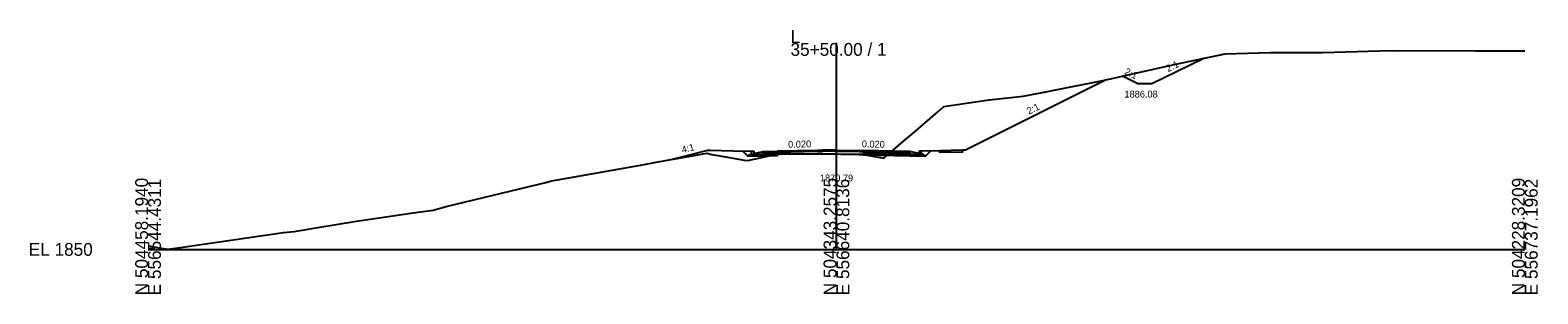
# Model space of a CAD drawing. Extents: x -26 to 4603, y -10 to 4703.
# Drawn here: x 974.3 to 1302.8, y 2685.3 to 2742.8 of the extents above; entities that cross this region are included whole.
import ezdxf

# ---------------------------------------------------------------- set-up
doc = ezdxf.new("R2010")
doc.units = 0
for name, color, linetype in [('Default', 7, 'Continuous'), ('Exist Cross Section Cell', 7, 'Continuous'), ('Exist XS Ground Line', 7, 'Continuous'), ('Prop CMT Pvmt Course 1', 7, 'Continuous'), ('Prop CMT Pvmt Course 2', 7, 'Continuous'), ('Prop CMT Pvmt Course 3', 7, 'Continuous'), ('Prop CMT Pvmt Milling', 7, 'Continuous'), ('Prop CMT Shear Line', 7, 'Continuous'), ('Prop CMT Shld Paved Course 2', 7, 'Continuous'), ('Prop CMT Shld Paved Course 3', 7, 'Continuous'), ('Prop CMT Subgrade Earthwork', 7, 'Continuous'), ('Prop Conc 4in Sidewalk', 7, 'Continuous'), ('Prop Conc Curb and Gutter', 7, 'Continuous'), ('Prop Corridor Mesh Bottom', 7, 'Continuous'), ('Prop XS Ditch Slope Text', 7, 'Continuous'), ('Prop XS Finish Grade', 7, 'Continuous'), ('Prop XS Label Text', 7, 'Continuous'), ('Prop XS SS Elevation Text', 7, 'Continuous'), ('Scratch_Level_9', 7, 'Continuous')]:
    doc.layers.add(name, color=color, linetype=linetype)

msp = doc.modelspace()

# ---------------------------------------------------------------- linework, layer by layer
at = {"layer": 'Exist Cross Section Cell'}
for p, q in [((1150, 2695), (1150, 2740)), ((1000, 2695), (1150, 2695)), ((1150, 2695), (1300, 2695))]:
    msp.add_line(p, q, dxfattribs=at)
at = {"layer": 'Exist XS Ground Line'}
msp.add_lwpolyline([(1000, 2695.79), (1002.92, 2695.3), (1004.3, 2695.07), (1007.08, 2695.4), (1029.54, 2698.68), (1031.83, 2698.92), (1036.96, 2699.78), (1045.39, 2701.12), (1057.75, 2702.96), (1062.16, 2703.55), (1064.95, 2704.32), (1086.95, 2709.68), (1087.38, 2709.79), (1087.99, 2709.92), (1090.42, 2710.36), (1107.33, 2713.37), (1111.55, 2714.14), (1112.36, 2714.32), (1113.57, 2714.53), (1117.8, 2715.26), (1121.77, 2715.96), (1122.88, 2715.72), (1126.7, 2715.04), (1129.9, 2714.47), (1130.66, 2714.36), (1135.7, 2715.46), (1137.17, 2715.73), (1145.86, 2715.83), (1146.93, 2715.85), (1154.98, 2715.7), (1155.89, 2715.69), (1157.05, 2715.48), (1160.32, 2714.9), (1161.24, 2715.75), (1162.47, 2716.72), (1164.58, 2718.61), (1167.26, 2720.75), (1172.01, 2724.94), (1173.38, 2726.17), (1183.28, 2727.57), (1190.72, 2728.38), (1195.97, 2729.43), (1208.4, 2731.9), (1214.24, 2733.17), (1223.96, 2735.35), (1234.72, 2737.65), (1244.5, 2737.91), (1256, 2737.95), (1268.35, 2738.27), (1271.74, 2738.35), (1289.34, 2738.29), (1297.84, 2738.26), (1298.59, 2738.27), (1299.75, 2738.28), (1300, 2738.28)], dxfattribs=at)
at = {"layer": 'Prop CMT Pvmt Course 1'}
for points in [[(1134, 2716.34), (1137.17, 2716.4), (1137.17, 2716.15), (1137.17, 2716.15), (1134, 2716.09), (1134, 2716.09), (1134, 2716.09), (1134, 2716.34), (1134, 2716.34)], [(1146.93, 2716.6), (1145.86, 2716.58), (1145.86, 2716.58), (1137.17, 2716.4), (1137.17, 2716.4), (1137.17, 2715.73), (1137.17, 2715.73), (1137.17, 2715.73), (1145.86, 2715.83), (1145.86, 2715.83), (1146.93, 2715.85), (1146.93, 2715.85), (1150, 2715.79), (1150, 2715.79), (1150, 2716.66), (1146.93, 2716.6), (1146.93, 2716.6)], [(1155.89, 2716.54), (1155.89, 2715.69), (1155.89, 2715.69), (1154.98, 2715.7), (1154.98, 2715.7), (1150, 2715.79), (1150, 2715.79), (1150, 2715.79), (1150, 2716.66), (1150, 2716.66), (1154.98, 2716.56), (1154.98, 2716.56), (1155.89, 2716.54)], [(1155.89, 2716.54), (1155.89, 2716.54), (1155.89, 2716.29), (1155.89, 2716.29), (1155.89, 2716.29), (1166, 2716.09), (1166, 2716.09), (1166, 2716.34), (1155.89, 2716.54)]]:
    msp.add_lwpolyline(points, dxfattribs=at)
at = {"layer": 'Prop CMT Pvmt Course 2'}
for points in [[(1134, 2716.09), (1137.17, 2716.15), (1137.17, 2715.82), (1137.17, 2715.82), (1134, 2715.76), (1134, 2715.76), (1134, 2715.76), (1134, 2716.09), (1134, 2716.09)], [(1155.89, 2716.29), (1155.89, 2716.29), (1155.89, 2715.96), (1155.89, 2715.96), (1155.89, 2715.96), (1166, 2715.76), (1166, 2715.76), (1166, 2716.09), (1155.89, 2716.29)]]:
    msp.add_lwpolyline(points, dxfattribs=at)
at = {"layer": 'Prop CMT Pvmt Course 3'}
for points in [[(1134, 2715.76), (1137.17, 2715.82), (1137.17, 2715.45), (1137.17, 2715.45), (1134, 2715.38), (1134, 2715.38), (1134, 2715.38), (1134, 2715.76), (1134, 2715.76)], [(1155.89, 2715.96), (1155.89, 2715.96), (1155.89, 2715.59), (1155.89, 2715.59), (1155.89, 2715.59), (1166, 2715.38), (1166, 2715.38), (1166, 2715.76), (1155.89, 2715.96)], [(1169, 2715.7), (1166, 2715.76), (1166, 2715.38), (1166, 2715.38), (1169.38, 2715.32), (1169.38, 2715.32), (1169.38, 2715.32), (1169, 2715.7), (1169, 2715.7)]]:
    msp.add_lwpolyline(points, dxfattribs=at)
at = {"layer": 'Prop CMT Pvmt Milling'}
for points in [[(1150, 2715.79), (1146.93, 2715.85), (1146.93, 2715.85), (1145.86, 2715.83), (1145.86, 2715.83), (1137.17, 2715.73), (1137.17, 2715.73)], [(1155.89, 2715.69), (1154.98, 2715.7), (1154.98, 2715.7), (1150, 2715.79), (1150, 2715.79)]]:
    msp.add_lwpolyline(points, dxfattribs=at)
at = {"layer": 'Prop CMT Shld Paved Course 2'}
for points in [[(1146.93, 2716.35), (1145.86, 2716.33), (1145.86, 2716.33), (1137.17, 2716.15), (1137.17, 2716.15), (1137.17, 2715.73), (1137.17, 2715.73), (1137.17, 2715.73), (1145.86, 2715.83), (1145.86, 2715.83), (1146.93, 2715.85), (1146.93, 2715.85), (1150, 2715.79), (1150, 2715.79), (1150, 2716.41), (1146.93, 2716.35), (1146.93, 2716.35)], [(1155.89, 2716.29), (1155.89, 2715.69), (1155.89, 2715.69), (1154.98, 2715.7), (1154.98, 2715.7), (1150, 2715.79), (1150, 2715.79), (1150, 2715.79), (1150, 2716.41), (1150, 2716.41), (1154.98, 2716.31), (1154.98, 2716.31), (1155.89, 2716.29)]]:
    msp.add_lwpolyline(points, dxfattribs=at)
at = {"layer": 'Prop CMT Shld Paved Course 3'}
msp.add_lwpolyline([(1131, 2715.7), (1134, 2715.76), (1134, 2715.38), (1134, 2715.38), (1130.7, 2715.32), (1130.7, 2715.32), (1130.7, 2715.32), (1131, 2715.7), (1131, 2715.7)], dxfattribs=at)
at = {"layer": 'Prop CMT Subgrade Earthwork'}
for points in [[(1129.54, 2716.48), (1130.7, 2715.32), (1130.7, 2715.32)], [(1130.7, 2715.32), (1130.7, 2715.32), (1137.17, 2715.45)], [(1169.38, 2715.32), (1155.89, 2715.59), (1155.89, 2715.59)], [(1170.55, 2716.48), (1169.38, 2715.32), (1169.38, 2715.32)]]:
    msp.add_lwpolyline(points, dxfattribs=at)
at = {"layer": 'Prop Conc 4in Sidewalk'}
msp.add_lwpolyline([(1172.5, 2716.52), (1172.5, 2716.52), (1172.49, 2716.19), (1172.49, 2716.19), (1172.49, 2716.19), (1177.51, 2716.29), (1177.51, 2716.29), (1177.5, 2716.62), (1172.5, 2716.52)], dxfattribs=at)
at = {"layer": 'Prop Conc Curb and Gutter'}
for points in [[(1132, 2715.94), (1134, 2716.34), (1134, 2715.76), (1134, 2715.76), (1131.5, 2715.71), (1131.5, 2715.71), (1131.5, 2715.71), (1131.5, 2716.44), (1131.5, 2716.44), (1132, 2716.44), (1132, 2715.94), (1132, 2715.94), (1132, 2715.94)], [(1168, 2715.94), (1166, 2716.34), (1166, 2715.76), (1166, 2715.76), (1168.5, 2715.71), (1168.5, 2715.71), (1168.5, 2715.71), (1168.5, 2716.44), (1168.5, 2716.44), (1168, 2716.44), (1168, 2715.94), (1168, 2715.94), (1168, 2715.94)]]:
    msp.add_lwpolyline(points, dxfattribs=at)
at = {"layer": 'Prop Corridor Mesh Bottom'}
msp.add_lwpolyline([(1166, 2716.34), (1166, 2716.09)], dxfattribs=at)
at = {"layer": 'Prop XS Finish Grade'}
msp.add_line((1122.5, 2716.62), (1127.5, 2716.52), dxfattribs=at)
for points in [[(1230.23, 2736.69), (1226.93, 2735.07), (1218.73, 2731.06)], [(1178, 2716.63), (1208.66, 2731.96)], [(1215.7, 2731.08), (1215.7, 2731.08), (1215.7, 2731.08), (1212.34, 2732.76)], [(1218.73, 2731.06), (1218.68, 2731.06), (1215.7, 2731.08)], [(1113.66, 2714.55), (1122, 2716.63), (1122, 2716.63)], [(1122, 2716.63), (1122.5, 2716.62), (1122.5, 2716.62)], [(1127.5, 2716.52), (1131.5, 2716.44), (1131.5, 2716.44)], [(1172.5, 2716.52), (1168.5, 2716.44), (1168.5, 2716.44)], [(1178, 2716.63), (1177.5, 2716.62), (1177.5, 2716.62)]]:
    msp.add_lwpolyline(points, dxfattribs=at)
at = {"layer": 'Scratch_Level_9'}
msp.add_lwpolyline([(1134, 2716.34), (1134, 2716.09)], dxfattribs=at)

# ---------------------------------------------------------------- texts
at = {"layer": 'Default'}
msp.add_text('-', height=0.0001, dxfattribs=at).set_placement((1000, 2695))
at = {"layer": 'Exist Cross Section Cell'}
for s, p in [('35+50.00 / 1', (1140, 2737.2)), ('L', (1140, 2740)), ('EL 1850', (974, 2693.6))]:
    msp.add_text(s, height=2.8, dxfattribs=at).set_placement(p)
for s, p in [('N 504458.1940', (1000, 2685)), ('N 504343.2575', (1150, 2685)), ('N 504228.3209', (1300, 2685)), ('E 556544.4311', (1002.8, 2685)), ('E 556640.8136', (1152.8, 2685)), ('E 556737.1962', (1302.8, 2685))]:
    msp.add_text(s, height=2.8, rotation=90, dxfattribs=at).set_placement(p)
at = {"layer": 'Prop CMT Shear Line'}
for p in [(1208.66, 2731.96), (1215.7, 2731.08), (1113.66, 2714.55), (1122, 2716.63), (1122.5, 2716.62), (1127.5, 2716.52), (1132, 2715.94), (1134, 2716.34), (1134, 2716.34), (1150, 2716.66), (1166, 2716.34), (1166, 2716.34), (1168, 2715.94), (1172.5, 2716.52), (1177.5, 2716.62), (1178, 2716.63)]:
    msp.add_text('X', height=0.0025, dxfattribs=at).set_placement(p)
at = {"layer": 'Prop XS Ditch Slope Text'}
msp.add_text('1886.08', height=1.5, dxfattribs=at).set_placement((1212.76, 2728.1))
at = {"layer": 'Prop XS Label Text'}
for s, rotation, p in [('2:1', 333.4349, (1212.64, 2733.3)), ('2:1', 26.5651, (1222.27, 2733.63)), ('2:1', 26.5651, (1191.92, 2724.37)), ('4:1', 14.0362, (1116.46, 2715.97)), ('0.020', 1.1458, (1139.48, 2717.15)), ('0.020', 358.8542, (1155.51, 2717.25))]:
    msp.add_text(s, height=1.5, rotation=rotation, dxfattribs=at).set_placement(p)
at = {"layer": 'Prop XS SS Elevation Text'}
msp.add_text('1870.79', height=1.5, dxfattribs=at).set_placement((1146.39, 2709.82))

doc.saveas('drawing.dxf')
